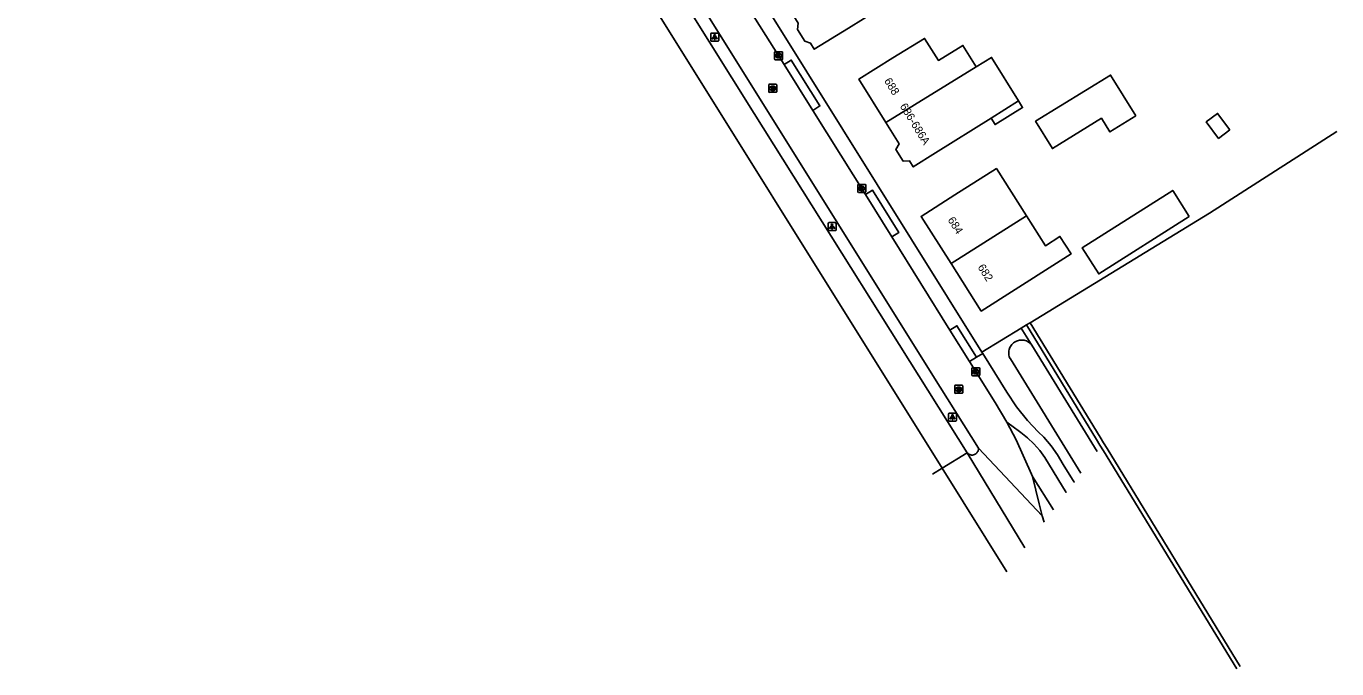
# Model space of a CAD drawing. Extents: x 158838 to 160074, y 386376 to 387776.
# Drawn here: x 159230.6 to 159394.4, y 386376.5 to 386456.8 of the extents above; entities that cross this region are included whole.
import ezdxf

# ---------------------------------------------------------------- set-up
doc = ezdxf.new("R2010")
doc.units = 0
for name, color, linetype in [('IMGEO_Berm_groen', 7, 'Continuous'), ('IMGEO_Fietspad_gesloten', 7, 'Continuous'), ('IMGEO_Groenvoorziening', 7, 'Continuous'), ('IMGEO_Haag', 7, 'Continuous'), ('IMGEO_Hek', 7, 'Continuous'), ('IMGEO_Kolk', 7, 'Continuous'), ('IMGEO_Lichtpunt', 7, 'Continuous'), ('IMGEO_Pand', 7, 'Continuous'), ('IMGEO_Pand_nummerreeks', 7, 'Continuous'), ('IMGEO_Pand_overbouw', 7, 'Continuous'), ('IMGEO_Rijbaan_lokaal_gesloten', 7, 'Continuous'), ('IMGEO_Rijbaan_lokaal_open', 7, 'Continuous'), ('IMGEO_Rijbaan_regionaal_gesloten', 7, 'Continuous'), ('IMGEO_Rioolput', 7, 'Continuous'), ('IMGEO_Voetpad_open', 7, 'Continuous'), ('IMGEO_Waterloop', 7, 'Continuous')]:
    doc.layers.add(name, color=color, linetype=linetype)

msp = doc.modelspace()

# ---------------------------------------------------------------- linework, layer by layer
at = {"layer": 'IMGEO_Berm_groen'}
for points in [[(159354.98, 386419.09), (159350.04, 386416.08)], [(159354.98, 386419.09), (159355.61, 386419.48)], [(159356.2, 386417.07), (159354.98, 386419.09)]]:
    msp.add_lwpolyline(points, dxfattribs=at)
at = {"layer": 'IMGEO_Fietspad_gesloten'}
msp.add_lwpolyline([(159356.38, 386400.53), (159358.99, 386396.36)], dxfattribs=at)
at = {"layer": 'IMGEO_Groenvoorziening'}
msp.add_lwpolyline([(159356.08, 386419.76), (159378.49, 386433.44), (159394.41, 386443.65), (159394.41, 386443.65)], dxfattribs=at)
at = {"layer": 'IMGEO_Haag'}
for points in [[(159355.61, 386419.48), (159355.9, 386419.65), (159356.08, 386419.76)], [(159355.61, 386419.48), (159364.37, 386405.15), (159364.8, 386404.45), (159365.24, 386403.72), (159381.9, 386376.48)], [(159356.08, 386419.76), (159364.84, 386405.43), (159365.27, 386404.73), (159365.71, 386404.01), (159382.35, 386376.78)]]:
    msp.add_lwpolyline(points, dxfattribs=at)
at = {"layer": 'IMGEO_Hek'}
for points in [[(159378.49, 386433.44), (159394.41, 386443.65)], [(159394.41, 386443.65), (159394.41, 386443.65)]]:
    msp.add_lwpolyline(points, dxfattribs=at)
at = {"layer": 'IMGEO_Kolk'}
for p, q in [((159324.15, 386452.71), (159324.15, 386453.56)), ((159324.22, 386453.64), (159325.07, 386453.64)), ((159324.63, 386453.42), (159324.66, 386453.42)), ((159325.15, 386453.56), (159325.15, 386452.71)), ((159325.07, 386452.64), (159324.22, 386452.64)), ((159324.66, 386452.86), (159324.63, 386452.86)), ((159334.53, 386436.11), (159334.53, 386436.97)), ((159334.61, 386437.04), (159335.46, 386437.04)), ((159335.02, 386436.82), (159335.05, 386436.82)), ((159335.53, 386436.97), (159335.53, 386436.11)), ((159335.46, 386436.04), (159334.61, 386436.04)), ((159335.04, 386436.26), (159335.02, 386436.26)), ((159348.8, 386413.19), (159348.8, 386414.04)), ((159348.87, 386414.12), (159349.73, 386414.12)), ((159349.29, 386413.9), (159349.31, 386413.9)), ((159349.8, 386414.04), (159349.8, 386413.19)), ((159349.73, 386413.12), (159348.87, 386413.12)), ((159349.31, 386413.34), (159349.29, 386413.34))]:
    msp.add_line(p, q, dxfattribs=at)
for points in [[(159324.15, 386452.71), (159324.15, 386453.56)], [(159324.22, 386453.64), (159325.07, 386453.64)], [(159324.47, 386453.34), (159324.59, 386453.34), (159324.59, 386453.18), (159324.72, 386453.34), (159324.88, 386453.34), (159324.74, 386453.19), (159324.89, 386452.94), (159324.74, 386452.94), (159324.65, 386453.1), (159324.59, 386453.03), (159324.59, 386452.94), (159324.47, 386452.94), (159324.47, 386453.34)], [(159325.15, 386453.56), (159325.15, 386452.71)], [(159325.07, 386452.64), (159324.22, 386452.64)], [(159334.53, 386436.11), (159334.53, 386436.97)], [(159334.61, 386437.04), (159335.46, 386437.04)], [(159335.53, 386436.97), (159335.53, 386436.11)], [(159335.46, 386436.04), (159334.61, 386436.04)], [(159334.85, 386436.74), (159334.98, 386436.74), (159334.98, 386436.59), (159335.11, 386436.74), (159335.27, 386436.74), (159335.12, 386436.59), (159335.28, 386436.34), (159335.12, 386436.34), (159335.04, 386436.51), (159334.98, 386436.44), (159334.98, 386436.34), (159334.85, 386436.34), (159334.85, 386436.74)], [(159348.8, 386413.19), (159348.8, 386414.04)], [(159348.87, 386414.12), (159349.73, 386414.12)], [(159349.8, 386414.04), (159349.8, 386413.19)], [(159349.73, 386413.12), (159348.87, 386413.12)], [(159349.12, 386413.82), (159349.24, 386413.82), (159349.24, 386413.66), (159349.37, 386413.82), (159349.54, 386413.82), (159349.39, 386413.67), (159349.54, 386413.42), (159349.39, 386413.42), (159349.31, 386413.58), (159349.24, 386413.51), (159349.24, 386413.42), (159349.12, 386413.42), (159349.12, 386413.82)]]:
    msp.add_lwpolyline(points, dxfattribs=at)
for centre, start, end in [((159324.22, 386453.56), 91.552, 178.448), ((159324.22, 386453.56), 91.552, 178.448), ((159325.07, 386453.56), 1.552, 88.448), ((159325.07, 386453.56), 1.552, 88.448), ((159324.22, 386452.71), 181.552, 268.448), ((159324.22, 386452.71), 181.552, 268.448), ((159325.07, 386452.71), 271.552, 358.448), ((159325.07, 386452.71), 271.552, 358.448), ((159334.61, 386436.97), 91.552, 178.448), ((159334.61, 386436.97), 91.552, 178.448), ((159335.46, 386436.97), 1.552, 88.448), ((159335.46, 386436.97), 1.552, 88.448), ((159334.61, 386436.12), 181.552, 268.448), ((159334.61, 386436.12), 181.552, 268.448), ((159335.46, 386436.12), 271.552, 358.448), ((159335.46, 386436.12), 271.552, 358.448), ((159348.88, 386414.04), 91.552, 178.448), ((159348.88, 386414.04), 91.552, 178.448), ((159349.72, 386414.04), 1.552, 88.448), ((159349.72, 386414.04), 1.552, 88.448), ((159348.88, 386413.19), 181.552, 268.448), ((159348.88, 386413.19), 181.552, 268.448), ((159349.72, 386413.19), 271.552, 358.448), ((159349.72, 386413.19), 271.552, 358.448)]:
    msp.add_arc(centre, 0.0765, start, end, dxfattribs=at)
for centre, major_axis, ratio, start_param, end_param in [((159324.63, 386453.14), (-0.387, 0.002), 0.722429, 4.712389, 7.853982), ((159324.66, 386453.14), (-0.39, 0.002), 0.717154, 1.570796, 4.712389), ((159335.02, 386436.54), (-0.387, 0.002), 0.722429, 4.712389, 7.853982), ((159335.04, 386436.54), (-0.39, 0.002), 0.717154, 1.570796, 4.712389), ((159349.29, 386413.62), (-0.387, 0.002), 0.722429, 4.712389, 7.853982), ((159349.31, 386413.62), (-0.39, 0.002), 0.717154, 1.570796, 4.712389)]:
    msp.add_ellipse(centre, major_axis=major_axis, ratio=ratio, start_param=start_param, end_param=end_param, dxfattribs=at)
at = {"layer": 'IMGEO_Lichtpunt'}
for p, q in [((159316.16, 386455.87), (159316.16, 386455.06)), ((159316.16, 386455.87), (159316.16, 386455.06)), ((159317.06, 386455.97), (159316.26, 386455.97)), ((159317.06, 386455.97), (159316.26, 386455.97)), ((159316.26, 386454.97), (159317.06, 386454.97)), ((159316.26, 386454.97), (159317.06, 386454.97)), ((159317.16, 386455.06), (159317.16, 386455.87)), ((159317.16, 386455.06), (159317.16, 386455.87)), ((159330.83, 386432.17), (159330.83, 386431.37)), ((159330.83, 386432.17), (159330.83, 386431.37)), ((159331.73, 386432.27), (159330.93, 386432.27)), ((159331.73, 386432.27), (159330.93, 386432.27)), ((159331.83, 386431.37), (159331.83, 386432.17)), ((159331.83, 386431.37), (159331.83, 386432.17)), ((159330.93, 386431.27), (159331.73, 386431.27)), ((159330.93, 386431.27), (159331.73, 386431.27)), ((159345.88, 386408.35), (159345.88, 386407.54)), ((159345.88, 386408.35), (159345.88, 386407.54)), ((159346.79, 386408.44), (159345.98, 386408.44)), ((159346.79, 386408.44), (159345.98, 386408.44)), ((159345.98, 386407.45), (159346.79, 386407.45)), ((159345.98, 386407.45), (159346.79, 386407.45)), ((159346.88, 386407.54), (159346.88, 386408.35)), ((159346.88, 386407.54), (159346.88, 386408.35))]:
    msp.add_line(p, q, dxfattribs=at)
for points in [[(159316.54, 386455.53), (159316.57, 386455.51), (159316.39, 386455.24), (159316.35, 386455.27), (159316.54, 386455.53)], [(159316.64, 386455.49), (159316.68, 386455.49), (159316.68, 386455.16), (159316.64, 386455.16), (159316.64, 386455.49)], [(159316.75, 386455.51), (159316.79, 386455.53), (159316.97, 386455.27), (159316.93, 386455.24), (159316.75, 386455.51)], [(159331.21, 386431.84), (159331.24, 386431.81), (159331.06, 386431.55), (159331.02, 386431.57), (159331.21, 386431.84)], [(159331.31, 386431.79), (159331.36, 386431.79), (159331.36, 386431.47), (159331.31, 386431.47), (159331.31, 386431.79)], [(159331.42, 386431.81), (159331.46, 386431.84), (159331.64, 386431.57), (159331.6, 386431.55), (159331.42, 386431.81)], [(159346.26, 386408.01), (159346.3, 386407.99), (159346.11, 386407.72), (159346.07, 386407.75), (159346.26, 386408.01)], [(159346.36, 386407.97), (159346.41, 386407.97), (159346.41, 386407.64), (159346.36, 386407.64), (159346.36, 386407.97)], [(159346.47, 386407.99), (159346.51, 386408.01), (159346.69, 386407.75), (159346.66, 386407.72), (159346.47, 386407.99)]]:
    msp.add_lwpolyline(points, dxfattribs=at)
for centre in [(159316.66, 386455.67), (159331.33, 386431.97), (159346.38, 386408.15)]:
    msp.add_circle(centre, 0.0994, dxfattribs=at)
for centre, start, end in [((159316.26, 386455.87), 90, 180), ((159316.26, 386455.87), 90, 180), ((159316.26, 386455.06), 180, 270), ((159316.26, 386455.06), 180, 270), ((159317.06, 386455.87), 0, 90), ((159317.06, 386455.87), 0, 90), ((159317.06, 386455.06), 270, 0), ((159317.06, 386455.06), 270, 360), ((159330.93, 386432.17), 90, 180), ((159330.93, 386432.17), 90, 180), ((159331.73, 386432.17), 0, 90), ((159331.73, 386432.17), 0, 90), ((159330.93, 386431.37), 180, 270), ((159330.93, 386431.37), 180, 270), ((159331.73, 386431.37), 270, 0), ((159331.73, 386431.37), 270, 360), ((159345.98, 386408.35), 90, 180), ((159345.98, 386408.35), 90, 180), ((159345.98, 386407.54), 180, 270), ((159345.98, 386407.54), 180, 270), ((159346.79, 386408.35), 0, 90), ((159346.79, 386408.35), 0, 90), ((159346.79, 386407.54), 270, 0), ((159346.79, 386407.54), 270, 360)]:
    msp.add_arc(centre, 0.0946, start, end, dxfattribs=at)
at = {"layer": 'IMGEO_Pand'}
for points in [[(159335.33, 386466.03), (159339.01, 386460.07), (159333.36, 386456.58), (159329.1, 386453.96), (159328.64, 386454.71), (159327.91, 386454.97), (159327.02, 386456.42), (159327.1, 386457.2), (159325.43, 386459.91)], [(159338.06, 386444.78), (159334.68, 386450.23), (159338.94, 386452.86), (159342.9, 386455.31), (159344.61, 386452.55), (159347.68, 386454.44), (159349.34, 386451.75)], [(159349.34, 386451.75), (159351.26, 386452.94), (159354.63, 386447.49), (159351.2, 386445.34), (159344.27, 386440.99), (159341.47, 386439.24), (159341.01, 386439.99), (159340.2, 386439.96), (159339.31, 386441.42), (159339.7, 386442.13), (159338.06, 386444.78)], [(159338.06, 386444.78), (159349.34, 386451.75)], [(159369.28, 386445.62), (159366.05, 386443.62), (159365, 386445.32), (159358.87, 386441.54), (159356.77, 386444.94), (159366.13, 386450.72), (159369.28, 386445.62)], [(159381.04, 386443.87), (159379.63, 386442.81), (159378.09, 386444.86), (159379.5, 386445.92), (159381.04, 386443.87)], [(159346.22, 386427.14), (159342.46, 386433.05), (159346.68, 386435.73), (159351.86, 386439.02), (159355.62, 386433.11)], [(159375.97, 386433.05), (159364.65, 386425.86), (159362.59, 386429.12), (159373.9, 386436.3), (159375.97, 386433.05)], [(159355.62, 386433.11), (159357.99, 386429.38), (159359.81, 386430.54), (159361.2, 386428.35), (159359.38, 386427.19), (159354.2, 386423.9), (159349.98, 386421.22), (159346.22, 386427.14)], [(159355.62, 386433.11), (159346.22, 386427.14)]]:
    msp.add_lwpolyline(points, dxfattribs=at)
at = {"layer": 'IMGEO_Pand_overbouw'}
msp.add_lwpolyline([(159351.2, 386445.34), (159351.7, 386444.54), (159355.14, 386446.66), (159354.63, 386447.49)], close=True, dxfattribs=at)
at = {"layer": 'IMGEO_Rijbaan_lokaal_gesloten'}
for points in [[(159349.61, 386404.05), (159349.61, 386404.01), (159349.61, 386403.94), (159349.61, 386403.88), (159349.59, 386403.81), (159349.57, 386403.74), (159349.55, 386403.67), (159349.52, 386403.61), (159349.48, 386403.55), (159349.44, 386403.5), (159349.39, 386403.44), (159349.34, 386403.4), (159349.29, 386403.35), (159349.23, 386403.32), (159349.17, 386403.28), (159349.1, 386403.26), (159349.04, 386403.23), (159348.97, 386403.22), (159348.9, 386403.21), (159348.83, 386403.21), (159348.76, 386403.21), (159348.69, 386403.22), (159348.62, 386403.24), (159348.56, 386403.26), (159348.49, 386403.29), (159348.43, 386403.32), (159348.37, 386403.36), (159348.32, 386403.4), (159348.27, 386403.45), (159348.22, 386403.5)], [(159357.58, 386395.62), (159349.61, 386404.05)], [(159357.58, 386395.62), (159357.83, 386394.81)]]:
    msp.add_lwpolyline(points, dxfattribs=at)
at = {"layer": 'IMGEO_Rijbaan_lokaal_open'}
for points in [[(159349.61, 386404.05), (159344.85, 386411.69), (159315.18, 386459.16), (159295.76, 386490.01), (159289.54, 386500), (159260.16, 386547.29), (159256.48, 386553.27)], [(159318.19, 386463.43), (159325.34, 386452.03)], [(159328.93, 386446.31), (159325.34, 386452.03)], [(159328.93, 386446.31), (159332.44, 386440.71), (159335.51, 386435.77)], [(159338.8, 386430.49), (159335.51, 386435.77)], [(159338.8, 386430.49), (159346.05, 386418.83)], [(159348.5, 386414.9), (159346.05, 386418.83)], [(159348.5, 386414.9), (159351.7, 386409.76), (159353.16, 386407.32)], [(159353.16, 386407.32), (159354.33, 386405.11), (159356.25, 386400.8), (159356.38, 386400.53)], [(159356.38, 386400.53), (159357.21, 386397.09), (159357.58, 386395.62)]]:
    msp.add_lwpolyline(points, dxfattribs=at)
at = {"layer": 'IMGEO_Rijbaan_regionaal_gesloten'}
for points in [[(159345.08, 386401.55), (159302.57, 386469.73), (159230.61, 386585.17)], [(159255.21, 386552.52), (159258.93, 386546.53), (159259.48, 386545.64), (159287.8, 386500), (159291.11, 386494.7), (159321.6, 386445.9), (159348.22, 386403.5)], [(159348.22, 386403.5), (159345.08, 386401.55)], [(159348.22, 386403.5), (159355.43, 386391.6)], [(159345.08, 386401.55), (159343.88, 386400.8)], [(159353.18, 386388.59), (159345.08, 386401.55)]]:
    msp.add_lwpolyline(points, dxfattribs=at)
at = {"layer": 'IMGEO_Rioolput'}
for p, q in [((159323.42, 386448.64), (159323.42, 386449.49)), ((159323.49, 386449.57), (159324.34, 386449.57)), ((159324.34, 386448.57), (159323.49, 386448.57)), ((159323.9, 386449.35), (159323.93, 386449.35)), ((159323.93, 386448.79), (159323.9, 386448.79)), ((159324.42, 386449.49), (159324.42, 386448.64)), ((159346.66, 386411), (159346.66, 386411.86)), ((159346.73, 386411.93), (159347.59, 386411.93)), ((159347.59, 386410.93), (159346.73, 386410.93)), ((159347.15, 386411.71), (159347.17, 386411.71)), ((159347.17, 386411.15), (159347.15, 386411.15)), ((159347.66, 386411.86), (159347.66, 386411))]:
    msp.add_line(p, q, dxfattribs=at)
for points in [[(159323.42, 386448.64), (159323.42, 386449.49)], [(159323.49, 386449.57), (159324.34, 386449.57)], [(159324.34, 386448.57), (159323.49, 386448.57)], [(159324.01, 386449.26), (159323.75, 386449.27), (159323.75, 386448.87)], [(159323.75, 386448.87), (159323.88, 386448.87), (159323.88, 386449.03), (159323.89, 386449.03)], [(159323.93, 386449.19), (159323.88, 386449.19), (159323.88, 386449.1)], [(159323.88, 386449.1), (159323.93, 386449.1)], [(159323.93, 386449), (159324.01, 386448.87), (159324.15, 386448.87), (159324.08, 386448.99)], [(159324.42, 386449.49), (159324.42, 386448.64)], [(159346.66, 386411), (159346.66, 386411.86)], [(159346.73, 386411.93), (159347.59, 386411.93)], [(159347.59, 386410.93), (159346.73, 386410.93)], [(159347.25, 386411.63), (159347, 386411.63), (159347, 386411.23)], [(159347, 386411.23), (159347.12, 386411.23), (159347.12, 386411.39), (159347.13, 386411.39)], [(159347.18, 386411.55), (159347.12, 386411.55), (159347.12, 386411.47)], [(159347.12, 386411.47), (159347.17, 386411.47)], [(159347.18, 386411.36), (159347.25, 386411.23), (159347.39, 386411.23), (159347.32, 386411.36)], [(159347.66, 386411.86), (159347.66, 386411)]]:
    msp.add_lwpolyline(points, dxfattribs=at)
for centre, radius, start, end in [((159323.49, 386449.49), 0.0765, 91.552, 178.448), ((159323.49, 386449.49), 0.0765, 91.552, 178.448), ((159323.49, 386448.64), 0.0765, 181.552, 268.448), ((159323.49, 386448.64), 0.0765, 181.552, 268.448), ((159323.89, 386448.98), 0.0533, 26.0293, 88.6989), ((159323.94, 386449.09), 0.0964, 77.0061, 93.1865), ((159323.91, 386449.29), 0.19, 274.7715, 282.9687), ((159323.95, 386449.15), 0.0378, 276.6634, 79.6772), ((159324, 386449.16), 0.109, 350.3612, 89.416), ((159324, 386449.15), 0.112, 277.5842, 350.9817), ((159323.99, 386448.94), 0.108, 29.5134, 73.7905), ((159324.34, 386449.49), 0.0765, 1.552, 88.448), ((159324.34, 386449.49), 0.0765, 1.552, 88.448), ((159324.34, 386448.64), 0.0765, 271.552, 358.448), ((159324.34, 386448.64), 0.0765, 271.552, 358.448), ((159346.74, 386411.85), 0.0765, 91.552, 178.448), ((159346.74, 386411.85), 0.0765, 91.552, 178.448), ((159346.74, 386411), 0.0765, 181.552, 268.448), ((159346.74, 386411), 0.0765, 181.552, 268.448), ((159347.13, 386411.34), 0.0533, 26.0293, 88.6989), ((159347.16, 386411.66), 0.19, 274.7715, 282.9687), ((159347.18, 386411.45), 0.0964, 77.0061, 93.1865), ((159347.2, 386411.51), 0.0378, 276.6634, 79.6772), ((159347.25, 386411.52), 0.109, 350.3612, 89.416), ((159347.25, 386411.52), 0.112, 277.5842, 350.9817), ((159347.23, 386411.3), 0.108, 29.5134, 73.7905), ((159347.58, 386411.85), 0.0765, 1.552, 88.448), ((159347.58, 386411.85), 0.0765, 1.552, 88.448), ((159347.58, 386411), 0.0765, 271.552, 358.448), ((159347.58, 386411), 0.0765, 271.552, 358.448)]:
    msp.add_arc(centre, radius, start, end, dxfattribs=at)
for centre, major_axis, ratio, start_param, end_param in [((159323.9, 386449.07), (-0.387, 0.002), 0.722429, 4.712389, 7.853982), ((159323.93, 386449.07), (-0.39, 0.002), 0.717154, 1.570796, 4.712389), ((159347.15, 386411.43), (-0.387, 0.002), 0.722429, 4.712389, 7.853982), ((159347.17, 386411.43), (-0.39, 0.002), 0.717154, 1.570796, 4.712389)]:
    msp.add_ellipse(centre, major_axis=major_axis, ratio=ratio, start_param=start_param, end_param=end_param, dxfattribs=at)
at = {"layer": 'IMGEO_Voetpad_open'}
for points in [[(159242.18, 386588.93), (159258.71, 386562.33), (159267.34, 386548.73), (159297.72, 386500), (159350.04, 386416.08)], [(159325.34, 386452.03), (159326.22, 386452.59), (159329.81, 386446.86), (159328.93, 386446.31)], [(159335.51, 386435.77), (159336.39, 386436.32), (159339.68, 386431.04), (159338.8, 386430.49)], [(159346.05, 386418.83), (159346.94, 386419.38), (159349.39, 386415.45)], [(159350.15, 386415.9), (159349.39, 386415.45)], [(159350.04, 386416.08), (159350.15, 386415.9)], [(159350.15, 386415.9), (159353.15, 386411.09), (159354.37, 386409.25), (159355.74, 386407.53), (159357.08, 386406.13), (159357.78, 386405.43), (159358.7, 386404.36), (159359.52, 386403.22), (159360.23, 386402.01), (159361.59, 386399.83), (159361.59, 386399.83)], [(159349.39, 386415.45), (159348.5, 386414.9)], [(159360.6, 386398.51), (159360.6, 386398.51), (159357.92, 386402.89), (159357.28, 386403.77), (159356.56, 386404.6), (159355.77, 386405.36), (159354.92, 386406.04), (159354.76, 386406.16), (159353.16, 386407.32)]]:
    msp.add_lwpolyline(points, dxfattribs=at)
at = {"layer": 'IMGEO_Waterloop'}
for points in [[(159362.42, 386400.93), (159353.61, 386415.23), (159353.58, 386415.27), (159353.52, 386415.4), (159353.48, 386415.54), (159353.44, 386415.68), (159353.42, 386415.82), (159353.41, 386415.96), (159353.42, 386416.1), (159353.43, 386416.25), (159353.46, 386416.39), (159353.51, 386416.52), (159353.56, 386416.66), (159353.63, 386416.79), (159353.7, 386416.91), (159353.79, 386417.02), (159353.89, 386417.12), (159353.99, 386417.22), (159354.11, 386417.31), (159354.23, 386417.38), (159354.36, 386417.45), (159354.49, 386417.5), (159354.63, 386417.54), (159354.77, 386417.57), (159354.91, 386417.59), (159355.05, 386417.59), (159355.2, 386417.58), (159355.34, 386417.56), (159355.48, 386417.52), (159355.61, 386417.47), (159355.74, 386417.41), (159355.87, 386417.34), (159355.99, 386417.26), (159356.1, 386417.17), (159356.2, 386417.07)], [(159364.46, 386403.66), (159364.46, 386403.66), (159356.29, 386416.96), (159356.2, 386417.07)]]:
    msp.add_lwpolyline(points, dxfattribs=at)

# ---------------------------------------------------------------- texts
at = {"layer": 'IMGEO_Pand_nummerreeks'}
for s, rotation, p in [('688', 301.719, (159337.79, 386450)), ('686-686A', 301.713, (159339.75, 386446.83)), ('684', 302.4191, (159345.73, 386432.61)), ('682', 302.4177, (159349.48, 386426.7))]:
    msp.add_text(s, height=1, rotation=rotation, dxfattribs=at).set_placement(p)

doc.saveas('drawing.dxf')
